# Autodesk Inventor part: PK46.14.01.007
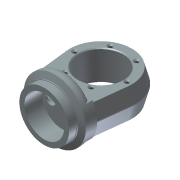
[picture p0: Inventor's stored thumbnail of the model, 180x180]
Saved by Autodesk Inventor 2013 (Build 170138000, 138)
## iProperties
Shininess: 64.0
Length Units: 11269
Angle Units: 11279
Time Units: 11290
Mass Units: 11283
Length Display Precision: 3
Angle Display Precision: 2
Compacted: True
Part Number: PK46.14.01.007
Document SubType Name: Modeling
Created: 2003-12
Material: Steel, Mild
Designer: NAndrey
Density: 7.86 g/cm^3
Density: 0.0
Volumn: 0.0
Area: 0.0
PropertySet Name: Model Information
Control State: 0
Master: False
Checked Out: False
Checked Out Date: 2008-10-15
Last Check In Date: 2008-10-15
Author: NAndrey
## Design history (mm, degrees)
sketch "Sketch1"
  geometry: L1 (-56.474, -70.317)-(-49.421, -132.418); L2 (-49.421, -132.418)-(75.579, -132.418); L3 (75.579, -132.418)-(82.632, -70.317); C1 r 45 at (13.079, -62.418); A1 r 70 centre (13.079, -62.418) between (82.632, -70.317) and (-56.474, -70.317)
  constraints: 6 end point, 2 centre point, 2 point on circle, 2 tangent, 1 coincident, 1 concentric, 1 equal length, 1 horizontal
  dimensions: "d1" = 140 diameter of A1; "d2" = 70 distance from line of L2 A1.centre; "d3" = 125 distance of L1.end L2.end; "d4" = 90 diameter of C1
extrude "Extrusion1" new body sketch "Sketch1" distance "d5" = 60; taper "d6" = 0 deg
workplane "Work Plane1"
sketch "Sketch2"
  geometry: L1 (75.579, -132.418)-(-49.421, -132.418) reference; L2 (-49.421, -132.418)-(75.579, -132.418) reference; L3 (13.079, -132.418)-(13.079, -182.578); L4 (-49.421, -132.418)-(-49.421, -155.232); L5 (-49.421, -155.232)-(-37.921, -159.418); L6 (-37.921, -159.418)-(-37.921, -161.418); L7 (-37.921, -161.418)-(-36.921, -161.418); L8 (-36.921, -161.418)-(-36.921, -176.418); L9 (-36.921, -176.418)-(-26.921, -176.418); L10 (-26.921, -176.418)-(-26.921, -140.418); L11 (-26.921, -140.418)-(13.079, -140.418); L12 (13.079, -140.418)-(13.079, -132.418)
  constraints: 20 end point, 6 parallel, 3 perpendicular, 1 collinear, 1 midpoint, 1 point on line
  dimensions: "d8" = 125 diameter of L4 L3 (derived); "d9" = 102 diameter of L6 L3; "d10" = 100 diameter of L8 L3; "d11" = 44 distance between parallel lines of L1 L9; "d12" = 20 deg angle of L9 L5; "d13" = 15 distance between parallel lines of L9 L7; "d14" = 17 distance from line of L5.end L9; "d15" = 80 diameter of L10 L3; "d16" = 36 distance between parallel lines of L9 L11
revolve "Revolution1" sketch "Sketch2" stored, may be unused: angle "d19" = 90 deg
chamfer "Chamfer1" distance "d20" = 29; stored, may be unused: angle "d21" = 15 deg, second distance "d57" = 29
chamfer "Chamfer2" distance "d22" = 29; stored, may be unused: angle "d23" = 15 deg, second distance "d58" = 29
workaxis "Work Axis1"
workplane "Work Plane2"
workplane "Work Plane3"
sketch "Sketch3"
  geometry: L1 (-69.393, 0)-(188.207, 0) reference; L2 (-32.593, -40)-(-32.593, 40) reference; 1 further point
  constraints: 1 point on line
  dimensions: "d25" = 49 distance from line of point (16.407, 0) L2
hole "Hole1" sketch "Sketch3" at (16.407, 0) diameter "d26" = 20; stored, may be unused: countersink angle "d30" = 82 deg, drill point angle "d32" = 120 deg; dims "d27" = 6, "d28" = 28, "d29" = 5, "d31" = 51
sketch "Sketch4"
  geometry: C1 r 14 at (0, 0) reference; C2 r 10 at (0, 0) reference
extrude "Extrusion2" cut sketch "Sketch4" stored distance "d33" = 60; taper "d34" = 0 deg
workaxis "Work Axis2"
sketch "Sketch5"
  geometry: L1 (-98, 0)-(98, 0) reference; C1 r 50 at (0, 0) reference; 1 further point
  constraints: 1 point on line
  dimensions: "d35" = 23 distance of C1.centre point (-23, 0)
hole "Hole2" sketch "Sketch5" at (-23, 0) diameter "d36" = 20; stored, may be unused: countersink angle "d40" = 82 deg, drill point angle "d42" = 118 deg; dims "d37" = 6, "d38" = 28, "d39" = 5, "d41" = 19
chamfer "Chamfer3" distance "d43" = 1.6; stored, may be unused: second distance "d44" = 2, angle "d59" = 45 deg
sketch "Эскиз6"
  geometry: A1 r 62.229 centre (13.079, -62.418) between (74.911, -69.44) and (-48.753, -69.44) reference; 1 further point
  dimensions: "d45" = 0 vertical distance of point (65.579, -62.418) A1.centre; "d46" = 52.5 distance of point (65.579, -62.418) A1.centre
hole "Отверстие3" sketch "Эскиз6" diameter "d47" = 6.647; stored, may be unused: countersink angle "d51" = 82 deg, drill point angle "d53" = 118 deg; dims "d48" = 18, "d49" = 11.2, "d50" = 2, "d52" = 23
node "РабОсь3"
pattern_circular "Круговой массив1" dims angle "d56" = 360 deg
mirror "ЗеркОтобр1"
sketch "Эскиз7"
  geometry: L1 (109.359, 0)-(0, 0) reference; L2 (1.602, -3)-(107.757, -3); A1 r 62.5 centre (54.68, 30) between (-6.437, 16.923) and (117.171, 28.968) reference
  constraints: 2 end point, 2 point on circle, 1 parallel
  dimensions: "d60" = 3 distance between parallel lines of L1 L2
extrude "Выдавливание3" cut sketch "Эскиз7" distance "d61" = 1; taper "d62" = 0 deg
fillet "Сопряжение1" dims "d63" = 15
node "РабОсь4"
node "РабПлоскость4"
mirror "ЗеркОтобр2"
body "Solid1"
node "Projected Loop1"
other parameters: "d24" = 90 deg, "d64" = 0
